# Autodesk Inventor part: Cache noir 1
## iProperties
Shininess: 20.0
Angle Display Precision: 2
Document Length Units: 11269
Document Angle Units: 11279
Document Time Units: 11290
Document Mass Units: 11283
Document Length Units Precision: 3
Document Angle Units Precision: 2
Created: 2002-09
Part Number: Cache noir 1
Material: Par défaut
Document SubType Name: Modélisation
Designer: administrateur
Density: 0.0
Volumn: 0.0
Area: 0.0
PropertySet Name: Model Information
Control State: 0
Master: False
Checked Out: False
Author: administrateur
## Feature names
1. Extrusion1
2. Extrusion2
3. Extrusion3
4. Extrusion4
5. Congé1 [Fillet]
6. Congé2 [Fillet]
